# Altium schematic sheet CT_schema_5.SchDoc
size 279 x 236 mm
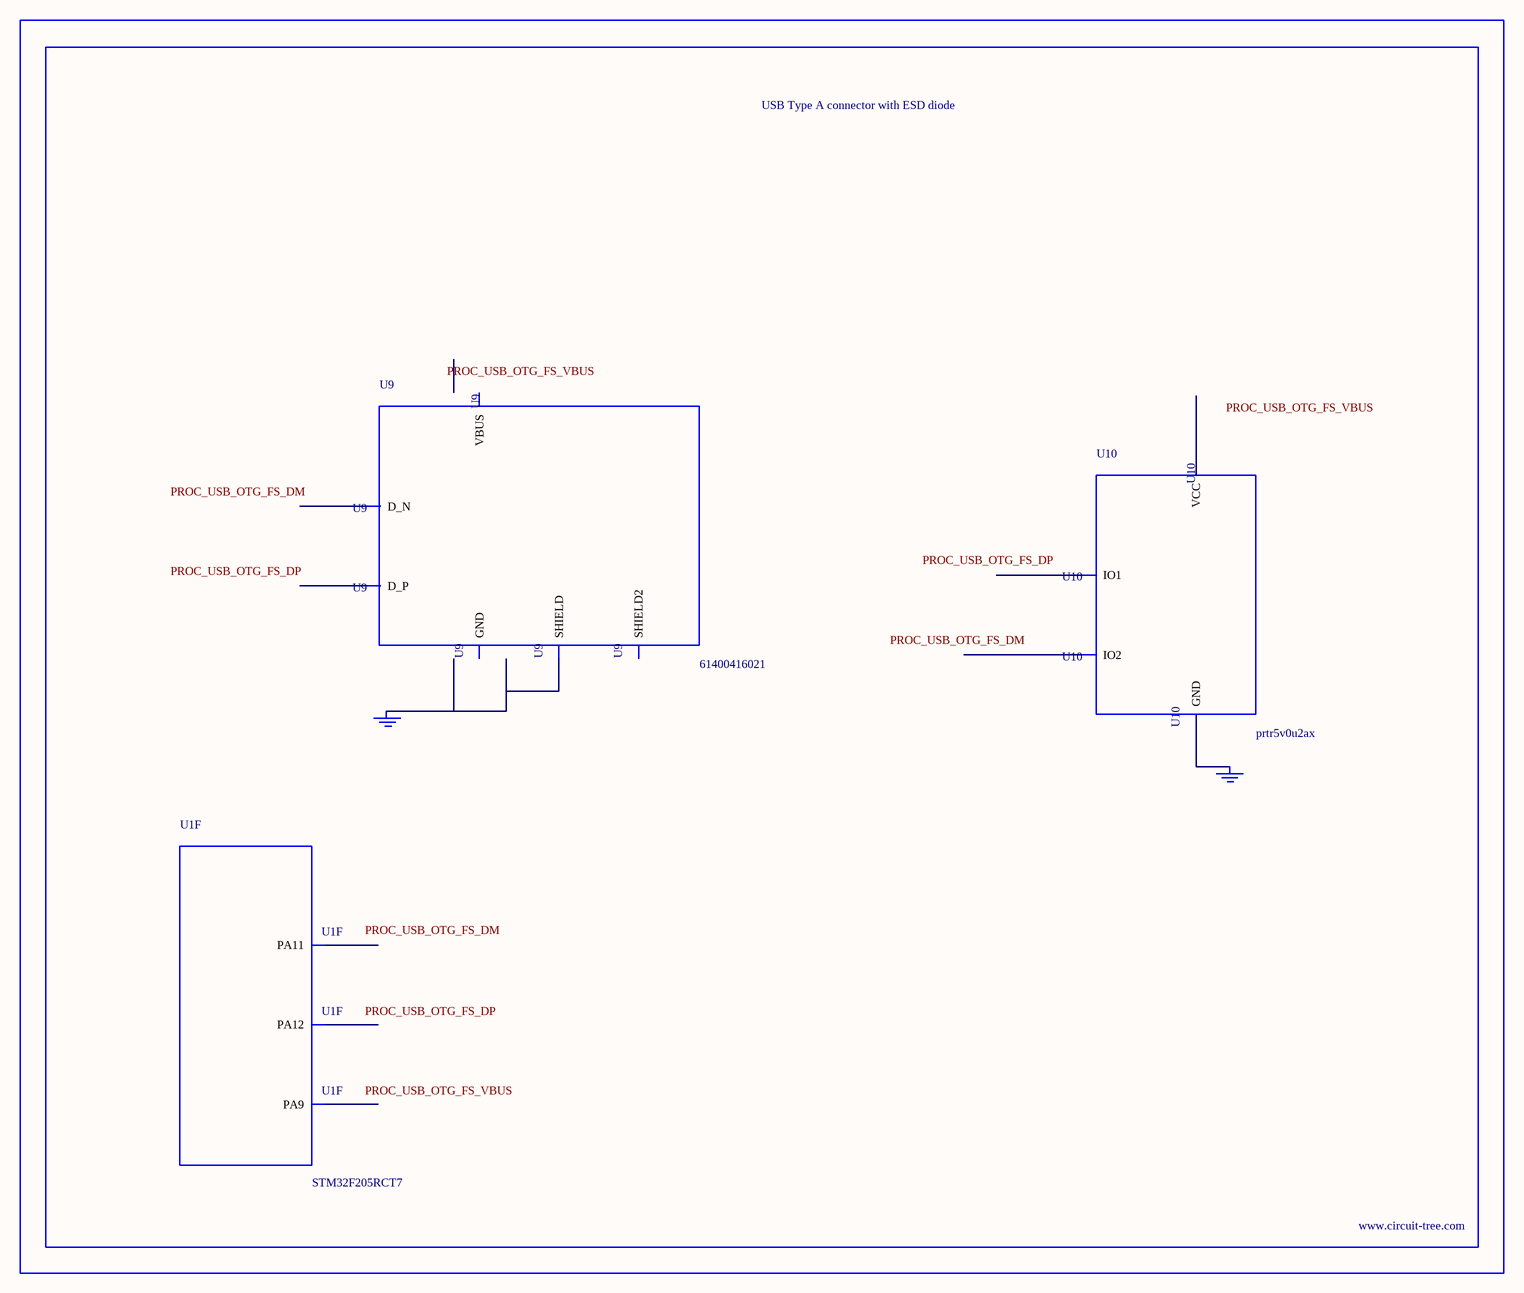
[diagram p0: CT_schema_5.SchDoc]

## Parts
BORDER4  (no value)
GND_INSTANCE_4_0  (no value)
GND_INSTANCE_4_1  (no value)
U1  STM32F205RCT7  [LQFP64]  (part F of 7)
U9  61400416021  [USB-A-H]
U10  prtr5v0u2ax  [SOT143B]

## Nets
NetGND_INSTANCE_4_0_0: GND_INSTANCE_4_0.0(GND) U9.5(SHIELD)
NetGND_INSTANCE_4_1_0: GND_INSTANCE_4_1.0(GND) U10.1(GND)

Not connected (* = marked no-connect by the designer): U1 42(PA9) 44(PA11) 45(PA12); U9 1(VBUS) 2(D_N) 3(D_P) 4(GND) 6(SHIELD2); U10 2(IO1) 3(IO2) 4(VCC)

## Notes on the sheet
- Labels drawn without touching a wire or pin: PROC_USB_OTG_FS_DM, PROC_USB_OTG_FS_DP, PROC_USB_OTG_FS_VBUS

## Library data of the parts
BORDER4 = BORDER_PAGE4
GND_INSTANCE_4_0 GND_INSTANCE_4_1 = GND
